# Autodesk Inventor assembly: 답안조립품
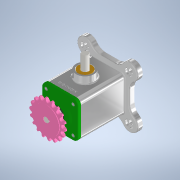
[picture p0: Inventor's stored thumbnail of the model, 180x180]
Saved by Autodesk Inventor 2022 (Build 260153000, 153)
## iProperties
Created: 2022-05
Part Number: 답안조립품
Document SubType Name: Assembly
Designer: admin
Author: admin
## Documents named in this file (11)
- C:\Users\admin\Desktop\720509V1010\답안조립품.iam
- C:\Users\admin\Desktop\720509V1010\본체.ipt
- C:\Users\admin\Desktop\720509V1010\커버.ipt
- C:\Users\admin\Desktop\720509V1010\베어링 6203.ipt
- C:\Users\admin\Desktop\720509V1010\편심축.ipt
- C:\Users\admin\Desktop\720509V1010\오일 실.ipt
- C:\Users\admin\Desktop\720509V1010\부시.ipt
- C:\Users\admin\Desktop\720509V1010\슬라이더.ipt
- C:\Users\admin\Desktop\720509V1010\키 4 x 4 x 14.ipt
- C:\Users\admin\Desktop\720509V1010\스프로킷.ipt
- C:\Users\admin\Desktop\720509V1010\볼트 M4.ipt
